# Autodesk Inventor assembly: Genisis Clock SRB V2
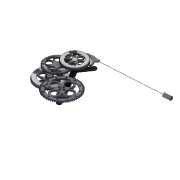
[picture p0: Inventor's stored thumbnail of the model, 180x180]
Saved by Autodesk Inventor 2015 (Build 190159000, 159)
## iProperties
Created: 2015-01
Part Number: Genisis Clock SRB V2
Document SubType Name: Assembly
Designer: Steve Brooks
RuleStatus: InUse
Author: Steve Brooks
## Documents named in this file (13)
- E:\Luke\Luke\Workspace\5 - Projects Home\Wooden clock\Genisis\Genisis Clock SRB V2.iam
- E:\Luke\Luke\Workspace\5 - Projects Home\Wooden clock\Genisis\Hour Gear.ipt
- E:\Luke\Luke\Workspace\5 - Projects Home\Wooden clock\Genisis\Gear click.ipt
- E:\Luke\Luke\Workspace\5 - Projects Home\Wooden clock\Genisis\Body.ipt
- E:\Luke\Luke\Workspace\5 - Projects Home\Wooden clock\Genisis\Pallet.ipt
- E:\Luke\Luke\Workspace\5 - Projects Home\Wooden clock\Genisis\Tick tock.ipt
- E:\Luke\Luke\Workspace\5 - Projects Home\Wooden clock\Genisis\Second  Gear .ipt
- E:\Luke\Luke\Workspace\5 - Projects Home\Wooden clock\Genisis\Gear 1 A.ipt
- E:\Luke\Luke\Workspace\5 - Projects Home\Wooden clock\Genisis\Minute Gear.ipt
- E:\Luke\Luke\Workspace\5 - Projects Home\Wooden clock\Genisis\Wind pulley.ipt
- E:\Luke\Luke\Workspace\5 - Projects Home\Wooden clock\Genisis\Hour Face.ipt
- E:\Luke\Luke\Workspace\5 - Projects Home\Wooden clock\Genisis\Second Face.ipt
- E:\Luke\Luke\Workspace\5 - Projects Home\Wooden clock\Genisis\Minute Face.ipt
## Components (13 placed, 12 different names)
1. Body:1 — Insert:3, Insert:4, Insert:31, Mate:9, Mate:12, Clock, Insert:45, Insert:46, Flush:2, Mate:16, Flush:3, Mate:17, Mate:19, Mate:20, Angle:4
2. Hour Gear:1 — Insert:4, Rotation:9, Flush:5
3. Minute Gear:1 — Rotation:9, Insert:31, Rotation:10, Flush:4
4. Gear click:1 — Insert:3, Mate:14
5. Pallet:1 — Flush:1, Mate:19, Mate:20, Angle:4
6. Tick tock:1 — Clock
7. Second  Gear :1 — Rotation:8, Mate:9, Flush:1, Mate:18, DRIVEME1
8. Gear 1 A:1 — Rotation:8, Mate:12, Rotation:10, Flush:5, Mate:18
9. Wind pulley:1 — Insert:45, Mate:14
10. Wind pulley:2 — Insert:46
11. Hour Face:1 — Flush:2, Mate:16
12. Second Face:1 — Flush:3, Mate:17
13. Minute Face:1 — Flush:4
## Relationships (24: Mate 8, Insert 5, Flush 5, RelateRotation 3, Angle 3)
- Insert:3: Body:1 ↔ Gear click:1
- Insert:4: Body:1 ↔ Hour Gear:1
- Rotation:8 [RelateRotation]: Second  Gear :1 ↔ Gear 1 A:1
- Rotation:9 [RelateRotation]: Hour Gear:1 ↔ Minute Gear:1
- Insert:31: Body:1 ↔ Minute Gear:1
- Mate:9: Body:1 ↔ Second  Gear :1
- Mate:12: Body:1 ↔ Gear 1 A:1
- Rotation:10 [RelateRotation]: Minute Gear:1 ↔ Gear 1 A:1
- Flush:1: Pallet:1 ↔ Second  Gear :1
- Clock [Angle]: Body:1 ↔ Tick tock:1
- Insert:45: Body:1 ↔ Wind pulley:1
- Mate:14: Gear click:1 ↔ Wind pulley:1
- Insert:46: Body:1 ↔ Wind pulley:2
- Flush:2: Body:1 ↔ Hour Face:1
- Mate:16: Body:1 ↔ Hour Face:1
- Flush:3: Body:1 ↔ Second Face:1
- Mate:17: Body:1 ↔ Second Face:1
- Flush:4: Minute Gear:1 ↔ Minute Face:1
- Flush:5: Hour Gear:1 ↔ Gear 1 A:1
- Mate:18: Second  Gear :1 ↔ Gear 1 A:1
- DRIVEME1 [Angle]: Second  Gear :1
- Mate:19: Body:1 ↔ Pallet:1
- Mate:20: Body:1 ↔ Pallet:1
- Angle:4: Body:1 ↔ Pallet:1
## Named parameters: SecondAngle = 7 deg, PendulumAngle = 9.04081 mm
